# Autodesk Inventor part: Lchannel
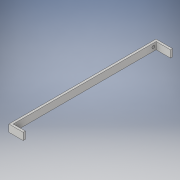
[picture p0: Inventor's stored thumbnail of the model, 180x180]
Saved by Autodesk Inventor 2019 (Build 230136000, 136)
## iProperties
Created: 2019-11
Part Number: Lchannel
Material: Generic
Document SubType Name: Sheet Metal
Designer: PRADYUMNA
Density: 1 g/cm^3
Sheet Metal Rule: Default_mm
Appearance: Default
Author: PRADYUMNA
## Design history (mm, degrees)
sketch "Sketch1"
  geometry: L1 (-5.488, 418.699)-(94.512, 418.699); L2 (94.512, 418.699)-(94.512, -581.301); L3 (94.512, -581.301)-(-5.488, -581.301); L4 (-5.488, -581.301)-(-5.488, 418.699); 1 further point
  constraints: 8 end point, 2 parallel, 1 horizontal, 1 perpendicular
  dimensions: "d0" = 1000 distance of L1.end L2.end; "d1" = 100 distance of L2.end L3.end
extrude "Extrusion1" new body sketch "Sketch1" distance "d2" = 50; taper "d3" = 0 deg
sketch "Sketch2"
  geometry: L1 (5.488, -418.699)-(5.488, 581.301) reference; L2 (5.488, -403.496)-(-79.218, -403.496); L3 (-79.218, -403.496)-(-79.218, 559.181); L4 (-79.218, 559.181)-(5.488, 559.181); L5 (5.488, 559.181)-(5.488, -403.496); 1 further point
  constraints: 8 end point, 2 parallel, 1 horizontal, 1 perpendicular, 1 point on line
extrude "Extrusion2" cut sketch "Sketch2" distance "d4" = 50; taper "d5" = 0 deg
sketch "Sketch3"
  geometry: C1 r 7.5 at (15.649, -25); 1 further point
  constraints: 1 centre point
  dimensions: "d6" = 15 diameter of C1
extrude "Extrusion3" cut sketch "Sketch3" distance "d7" = 50; taper "d8" = 0 deg
sketch "Sketch4"
  geometry: C1 r 10 at (945.331, -25); 1 further point
  constraints: 1 centre point
  dimensions: "d9" = 20 diameter of C1
extrude "Extrusion4" cut sketch "Sketch4" distance "d10" = 50; taper "d11" = 0 deg
thread "Thread1" dims "d12" = 10, "d13" = 0
thread "Thread2" dims "d14" = 10, "d15" = 0
sketch "Sketch5"
  geometry: 1 further point
sketch "Sketch6"
  geometry: C1 r 5 at (97.751, 25); C2 r 5 at (154.597, 25); C3 r 5 at (216.48, 25); C4 r 5 at (270.448, 25); C5 r 5 at (328.013, 25); C6 r 5 at (392.055, 25); C7 r 5 at (460.413, 25); C8 r 5 at (524.455, 25); C9 r 5 at (581.301, 25); C10 r 5 at (657.575, 25); C11 r 5 at (722.336, 25); C12 r 5 at (820.197, 25); C13 r 5 at (771.986, 25); C14 r 5 at (890.715, 25); 1 further point
  constraints: 14 centre point
  dimensions: "d16" = 10 diameter of C1; "d17" = 10 diameter of C2; "d18" = 10 diameter of C3; "d19" = 10 diameter of C4; "d20" = 10 diameter of C5; "d21" = 10 diameter of C6; "d22" = 10 diameter of C7; "d23" = 10 diameter of C8; "d24" = 10 diameter of C9; "d25" = 10 diameter of C10; "d26" = 10 diameter of C11; "d27" = 10 diameter of C12; "d28" = 10 diameter of C13; "d29" = 10 diameter of C14
extrude "Extrusion5" join sketch "Sketch6" distance "d30" = 10; taper "d31" = 0 deg
sketch "Sketch7"
  geometry: L1 (913.068, 23.573)-(994.977, 23.573); L2 (994.977, 23.573)-(994.977, -84.431); L3 (994.977, -84.431)-(913.068, -84.431); L4 (913.068, -84.431)-(913.068, 23.573); 1 further point
  constraints: 8 end point, 2 parallel, 1 horizontal, 1 perpendicular
extrude "Extrusion6" cut sketch "Sketch7" stored distance "d32" = 1000; taper "d33" = 0 deg
sketch "Sketch8"
  geometry: L1 (0, 50)-(15.294, 50) reference; L2 (0, 0)-(0, 50) reference; L3 (15.294, 50)-(0, 50); L4 (0, 50)-(0, 0); L5 (0, 0)-(15.294, 0); L6 (15.294, 0)-(15.294, 50); 1 further point
  constraints: 8 end point, 2 parallel, 1 horizontal, 1 perpendicular
extrude "Extrusion7" join sketch "Sketch8" distance "d34" = 100; taper "d35" = 0 deg
sketch "Sketch9"
  geometry: L1 (1013.068, 50)-(1013.068, 0) reference; L2 (1013.068, 50)-(998.17, 50); L3 (998.17, 50)-(998.17, 0); L4 (998.17, 0)-(1013.068, 0); L5 (1013.068, 0)-(1013.068, 50); 1 further point
  constraints: 8 end point, 2 parallel, 1 horizontal, 1 perpendicular
extrude "Extrusion8" join sketch "Sketch9" distance "d36" = 100; taper "d37" = 0 deg
sketch "Sketch10"
  geometry: C1 r 10 at (978.602, 26.681); 1 further point
  constraints: 1 centre point
  dimensions: "d38" = 20 diameter of C1
extrude "Extrusion9" cut sketch "Sketch10" distance "d39" = 100; taper "d40" = 0 deg
thread "Thread3" dims "d41" = 10, "d42" = 0
body "Solid1"
other parameters: "Thickness" = 0.5, "BendRadius" = 0.5 (= Thickness), "BendReliefWidth" = 0.5 (= Thickness), "BendReliefDepth" = 0.25 (= 0.5 x Thickness), "CornerReliefSize" = 2 (= 4 x Thickness), "SeamGap" = 0.01, "MinimumRemnant" = 1 (= 2 x Thickness), "TransitionRadius" = 0.5 (= BendRadius), "JacobiRadiusSize" = 0.5 (= BendRadius), "GapSize" = 0.5 (= Thickness)
